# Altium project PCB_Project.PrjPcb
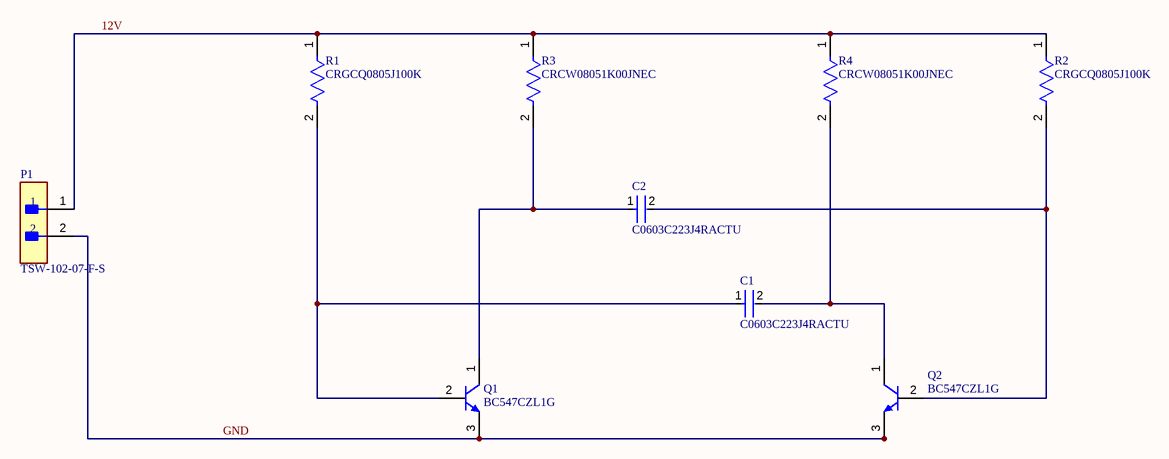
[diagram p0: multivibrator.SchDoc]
1 sheet, 9 parts. Net scope: global (net labels, ports and power ports of the same name join across sheets).
Board file: multivibrator.PcbDoc

## Sheet multivibrator.SchDoc
size 431 x 279 mm; SheetNumber: 1; SheetTotal: 1; ENG_APP_DATE: --/--/--; DSN_APP_DATE: --/--/--; CHK_APP_DATE: --/--/--

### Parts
C1  C0603C223J4RACTU  [FP-C0603C-CF-MFG]
C2  C0603C223J4RACTU  [FP-C0603C-CF-MFG]
P1  TSW-102-07-F-S  [FP-TSW-102-07-F-S-MFG]
Q1  BC547CZL1G  [ONSC-TO-92-3-29-11_AM_BL]
Q2  BC547CZL1G  [ONSC-TO-92-3-29-11_AM_BL]
R1  CRGCQ0805J100K  [FP-CRGCQ0805-IPC_C]
R2  CRGCQ0805J100K  [FP-CRGCQ0805-IPC_C]
R3  CRCW08051K00JNEC  [FP-CRCW0805-e3-IPC_A]
R4  CRCW08051K00JNEC  [FP-CRCW0805-e3-IPC_A]

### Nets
12V: P1.1 R1.1 R2.1 R3.1 R4.1
GND: P1.2 Q1.3(E) Q2.3(E)
NetC1_1: C1.1 Q1.2(B) R1.2
NetC1_2: C1.2 Q2.1(C) R4.2
NetC2_1: C2.1 Q1.1(C) R3.2
NetC2_2: C2.2 Q2.2(B) R2.2

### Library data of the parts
C1 C2 = CMP-2006-03745-2: CAP CER 0.022UF 16V 5% X7R 0603; Manufacturer: KEMET; Tolerance: 0.05; Automotive Grade: Grade 1; Temperature Coefficient: 30ppm/°C; Capacitance: 22,000 pF; Material: Ceramic; Value: 22,000 pF
P1 = CMP-02766-001458-1: CONN HEADER VERT 2POS 2.54MM; Gender: Male; Max Current Rating: 7.6A; Number of Contacts: 2; Max Voltage Rating (AC): 550V
Q1 Q2 = CMP-1048-01606-1: Amplifier Transistor, NPN Silicon, 3-Pin TO-92, Pb-Free, Ammo Box; Manufacturer: On Semiconductor; IC Continuous (A): 0.1; fT Min (MHz): 150
R1 R2 = CMP-03211-009742-1: CRGCQ0805 100KΩ 0.125W ±100ppm/°C 5% 150V; Manufacturer: TE Connectivity; Tolerance: 0.05
R3 R4 = CMP-02407-005778-1: RES Thick Film, 1kΩ, 5%, 0.125W, 200ppm/°C, 0805; Max Power Dissipation: 125mW; Resistance: 1kR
